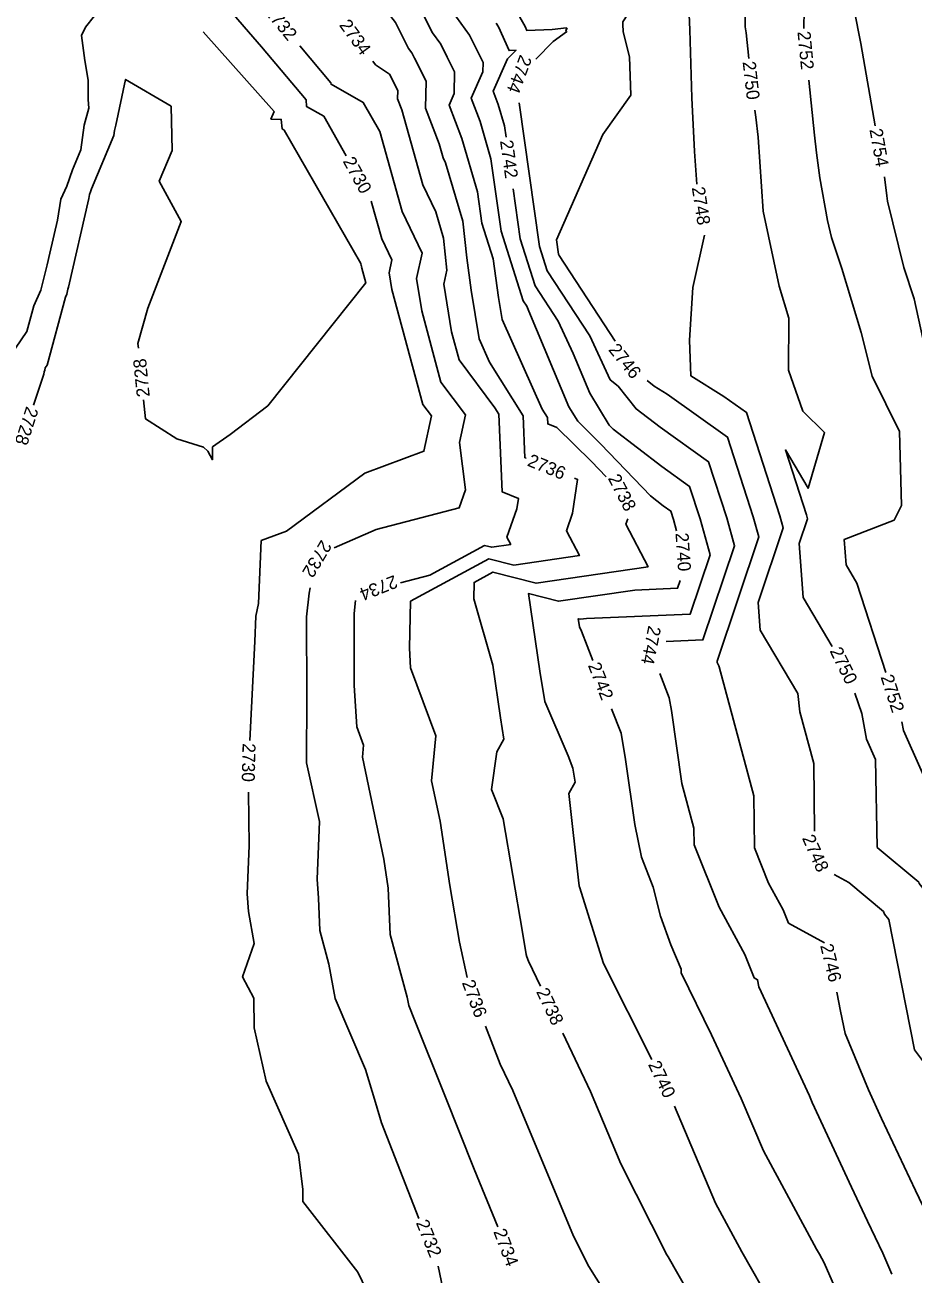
# Model space of a CAD drawing. Extents: x 1326424 to 1329294, y 1001359 to 1003823.
# Drawn here: x 1327989.8 to 1328126.5, y 1002687.1 to 1002879.4 of the extents above; entities that cross this region are included whole.
import ezdxf

# ---------------------------------------------------------------- set-up
doc = ezdxf.new("R2010")
doc.units = 0
doc.layers.add('Prop Rem of Exist Asph Pvmt', color=7, linetype='Continuous')
doc.layers.add('Scratch_Level_3', color=7, linetype='Continuous')

msp = doc.modelspace()

# ---------------------------------------------------------------- linework, layer by layer
at = {"layer": 'Prop Rem of Exist Asph Pvmt'}
for points in [[(1328051.65, 1002889.76), (1328056.26, 1002880.64), (1328058.26, 1002877.87), (1328059.82, 1002874.69), (1328060.32, 1002873.7), (1328060.3, 1002872.23), (1328058.49, 1002868.19), (1328059.86, 1002864.59), (1328061.54, 1002858.85), (1328063.1, 1002847.74), (1328066.52, 1002836.98), (1328067.05, 1002836.17), (1328067.39, 1002835.43), (1328073.55, 1002820.7), (1328074.9, 1002818.48), (1328078.48, 1002814.95), (1328086.09, 1002806.97), (1328088.07, 1002805.44), (1328089.21, 1002804.63), (1328089.64, 1002803.32), (1328090.12, 1002801.59)], [(1328090.67, 1002793.93), (1328090.28, 1002792.77), (1328083.71, 1002792.49), (1328071.92, 1002790.76), (1328067.3, 1002791.95), (1328069.06, 1002779.98), (1328069.81, 1002775.31), (1328073.43, 1002766.96), (1328074.17, 1002765.05), (1328074.53, 1002762.91), (1328073.54, 1002761.16), (1328075.08, 1002747.38), (1328075.1, 1002746.99), (1328075.12, 1002746.92), (1328075.16, 1002746.82), (1328078.89, 1002735.03), (1328086.33, 1002720.24)], [(1328089.78, 1002713.03), (1328096.09, 1002698.14), (1328100.16, 1002690.63), (1328104.83, 1002682.41), (1328112.07, 1002668.46), (1328113.08, 1002666.12), (1328113.65, 1002664.98), (1328121.1, 1002646.94), (1328124.03, 1002640.73), (1328127.87, 1002626.26), (1328128.6, 1002621.38)]]:
    msp.add_lwpolyline(points, dxfattribs=at)
at = {"layer": 'Scratch_Level_3'}
for points in [[(1328085.81, 1002968.7), (1328086.63, 1002966.04), (1328090.35, 1002953.28), (1328091.18, 1002947.31), (1328092.72, 1002942.62), (1328094.13, 1002935.83), (1328095.88, 1002929.47), (1328099.81, 1002908.73), (1328099.75, 1002906.54), (1328099.72, 1002899.04), (1328101.73, 1002895.42), (1328100.93, 1002893.21), (1328102.1, 1002893.19), (1328103.76, 1002892.22), (1328102.34, 1002890.38), (1328100.61, 1002888.24), (1328100.7, 1002879.15), (1328100.82, 1002878.25), (1328101.25, 1002874.29)], [(1328099.88, 1002962.54), (1328098.3, 1002956.73), (1328097.58, 1002953.88), (1328096.58, 1002949.91), (1328095.11, 1002952.77), (1328093.95, 1002955.15), (1328097.18, 1002944.23), (1328098.29, 1002940.01), (1328100.88, 1002931.08), (1328103.34, 1002920.89), (1328106.21, 1002906.84), (1328107.1, 1002905.24), (1328106.44, 1002901.86), (1328106.14, 1002901.14), (1328109.72, 1002898.83), (1328110.63, 1002896.22), (1328111.23, 1002895.33), (1328109.89, 1002890.42), (1328109.34, 1002890.17), (1328109.82, 1002889.18), (1328109.88, 1002887.57), (1328109.7, 1002878.92)], [(1328067.16, 1002959.87), (1328067.39, 1002958.02), (1328073.63, 1002943.56), (1328074.36, 1002941.37), (1328077.21, 1002923.05), (1328078.72, 1002918.69), (1328078.4, 1002909.97), (1328078.39, 1002909.93), (1328077.48, 1002903.22), (1328069.35, 1002892.65), (1328068.98, 1002892.21), (1328068.87, 1002891.89), (1328065.97, 1002880.64), (1328066.81, 1002879.19), (1328067.08, 1002878.59), (1328070.95, 1002878.74), (1328073.19, 1002879.01), (1328073.25, 1002878.89), (1328073.08, 1002878.63), (1328073.18, 1002878.37), (1328071.11, 1002876.89), (1328068.44, 1002874.18)], [(1328083.58, 1002950.21), (1328083.6, 1002950.12), (1328087.44, 1002938.56), (1328087.53, 1002937.99), (1328087.94, 1002936.8), (1328092.09, 1002921.74), (1328093.86, 1002912.39), (1328093.51, 1002900.34), (1328093.5, 1002897.26), (1328094.32, 1002895.78), (1328093.21, 1002892.72), (1328091.7, 1002888.2), (1328091.99, 1002887.57), (1328093.97, 1002887.44), (1328092.27, 1002884.67), (1328091.73, 1002884), (1328091.74, 1002883.05), (1328092.1, 1002880.28), (1328092.12, 1002879.86), (1328092.16, 1002878.68), (1328092.46, 1002868.22), (1328092.87, 1002860), (1328093.21, 1002854.94)], [(1328039.27, 1002859.33), (1328035.79, 1002865.4), (1328033.17, 1002866.88), (1328033.07, 1002867.93), (1328026.24, 1002876.08), (1328020.59, 1002882.62), (1328016.38, 1002886.94), (1328013.75, 1002890.69), (1328009.71, 1002895.02), (1328008.12, 1002896.57), (1328004.64, 1002901.8), (1327996.95, 1002909.58), (1327996.48, 1002909.87), (1327993.92, 1002914.01), (1327990.52, 1002919.55), (1327992, 1002922.95), (1327992.64, 1002931.97), (1327993.9, 1002939.8), (1327994.15, 1002940.85)], [(1328085.17, 1002922.41), (1328087.42, 1002915.9), (1328087.37, 1002914.57), (1328087.34, 1002913.06), (1328086.63, 1002897.49), (1328083.46, 1002886.47), (1328082.73, 1002885.6), (1328082.36, 1002884.53), (1328083.04, 1002884.62), (1328083.86, 1002883.04), (1328083.29, 1002882.15), (1328081.82, 1002879.93), (1328081.84, 1002879.56), (1328081.88, 1002878.4), (1328082.87, 1002874.54), (1328083.08, 1002868.65), (1328078.77, 1002862.61), (1328071.65, 1002846.37), (1328071.95, 1002844.17), (1328072.03, 1002843.95), (1328080.66, 1002830.79)], [(1328029.87, 1002902.46), (1328030.64, 1002901.4), (1328037.21, 1002895.24), (1328038.38, 1002893.35), (1328039.53, 1002892.3), (1328042.38, 1002885.63), (1328046.86, 1002879.81), (1328048.86, 1002875.84), (1328049.36, 1002875.14), (1328049.75, 1002874.35), (1328051.57, 1002870.81), (1328051.49, 1002866.63), (1328053.59, 1002861.15), (1328054.18, 1002859.02), (1328054.56, 1002858.24), (1328057.19, 1002849.24), (1328057.81, 1002843.63), (1328058.51, 1002838.66), (1328059.72, 1002831.16), (1328061.34, 1002827.55), (1328066.5, 1002819.3), (1328066.77, 1002812.84), (1328066.98, 1002812.76)], [(1328041.49, 1002899.21), (1328041.77, 1002899.04), (1328044.25, 1002893.98), (1328045.73, 1002890.53), (1328047.55, 1002888.15), (1328052.56, 1002878.24), (1328053.81, 1002876.51), (1328054.78, 1002874.52), (1328055.94, 1002872.25), (1328055.89, 1002868.89), (1328055.1, 1002867.13), (1328057.06, 1002861.98), (1328059.47, 1002853.75), (1328060.15, 1002848.93), (1328061.89, 1002843.45), (1328062.72, 1002837.52), (1328063.27, 1002834.13), (1328069.45, 1002820.31), (1328070.24, 1002819.05), (1328070.28, 1002818.06), (1328071.7, 1002817.48), (1328077.01, 1002812.25), (1328079.26, 1002809.89)], [(1328116.44, 1002887.03), (1328118.46, 1002876.59), (1328120.71, 1002863.94)], [(1327988.33, 1002829.71), (1327990.12, 1002832.28), (1327991.18, 1002836.21), (1327992.26, 1002838.63), (1327993.23, 1002842.54), (1327993.63, 1002844.31), (1327994.8, 1002849.42), (1327995.32, 1002852.66), (1327996.23, 1002854.66), (1327997.12, 1002857.17), (1327998.4, 1002860.25), (1327998.91, 1002864.01), (1327999.65, 1002866.67), (1327999.55, 1002867.96), (1327999.53, 1002870.97), (1327999.01, 1002873.98), (1327998.5, 1002877.85), (1327999.12, 1002879.09), (1328001.91, 1002882.6)], [(1328008.07, 1002821.77), (1328008.37, 1002818.81), (1328013.17, 1002815.77), (1328017.27, 1002814.49), (1328017.96, 1002813.88), (1328018.7, 1002812.55), (1328018.67, 1002814.5), (1328021.42, 1002816.41), (1328027.17, 1002820.81), (1328042.26, 1002839.78), (1328041.66, 1002842.02), (1328041.63, 1002842.14), (1328041.66, 1002842.25), (1328041.58, 1002842.41), (1328041.49, 1002842.73), (1328029.72, 1002863.28), (1328029.41, 1002863.45), (1328029.27, 1002864.91), (1328027.68, 1002864.97), (1328028.15, 1002866.13), (1328017.23, 1002878.4)], [(1328062.33, 1002879.75), (1328062.68, 1002879.14), (1328064.34, 1002875.51), (1328065.41, 1002875.55), (1328064.11, 1002874.23), (1328061.88, 1002869.25), (1328062.66, 1002867.21), (1328063.62, 1002863.94), (1328063.86, 1002862.16)], [(1328032.11, 1002876.26), (1328036.91, 1002870.54), (1328036.94, 1002870.32), (1328041.87, 1002867.53), (1328044.42, 1002863.07), (1328047.88, 1002850.72), (1328050.94, 1002844.34), (1328050.08, 1002840.43), (1328050.88, 1002835.48), (1328053.85, 1002824.48), (1328057.62, 1002819.43), (1328056.71, 1002815.19), (1328057.62, 1002807.89), (1328056.65, 1002805.14), (1328043.86, 1002801.78), (1328037.38, 1002798.97)], [(1328043.34, 1002873.89), (1328043.77, 1002873.3), (1328045.9, 1002871.88), (1328047.19, 1002869.36), (1328047.16, 1002868.07), (1328047.81, 1002866.39), (1328051.03, 1002854.87), (1328053.05, 1002850.67), (1328054.23, 1002846.64), (1328054.77, 1002841.72), (1328054.3, 1002839.57), (1328055.49, 1002832.22), (1328056.65, 1002827.9), (1328062.15, 1002820.52), (1328062.76, 1002819.55), (1328063.25, 1002807.62), (1328065.78, 1002806.59), (1328065.54, 1002804.97), (1328064.01, 1002800.62), (1328064.59, 1002799.5), (1328061.66, 1002799.07), (1328060.53, 1002799.36), (1328052.12, 1002794.78), (1328047.6, 1002793.6)], [(1327991.14, 1002820.94), (1327992.73, 1002825.7), (1327992.77, 1002826.06), (1327992.85, 1002826.35), (1327992.94, 1002826.69), (1327993.2, 1002827.07), (1327996.03, 1002837.54), (1327996.24, 1002838.01), (1327996.43, 1002838.78), (1327996.5, 1002839.12), (1327999.62, 1002852.74), (1327999.72, 1002853.37), (1327999.9, 1002853.76), (1328000.07, 1002854.25), (1328003.48, 1002862.46), (1328003.58, 1002863.19), (1328003.81, 1002864.03), (1328005.3, 1002871.06), (1328012.29, 1002866.95), (1328012.46, 1002860.15), (1328010.49, 1002855.42), (1328013.86, 1002849.19), (1328008.7, 1002835.86), (1328007.19, 1002830.45), (1328007.26, 1002829.72)], [(1328110.47, 1002870.96), (1328111.35, 1002862.51), (1328111.68, 1002859.77), (1328112.17, 1002855.94), (1328113.35, 1002849.37), (1328113.99, 1002846.76), (1328115.54, 1002841.97), (1328118.52, 1002832.11), (1328120.24, 1002825.39), (1328124.43, 1002816.88), (1328124.73, 1002805.52), (1328123.6, 1002803.24), (1328115.93, 1002800.27), (1328116.2, 1002796.36), (1328117.88, 1002793.54), (1328122.32, 1002779.81)], [(1328065.91, 1002867.46), (1328069, 1002845.36), (1328070.19, 1002841.63), (1328076.77, 1002831.59), (1328079.88, 1002824.85), (1328081.15, 1002823.86), (1328083.89, 1002820.37), (1328087.59, 1002817.53), (1328095.04, 1002812.22), (1328097.83, 1002803.62), (1328099.04, 1002799.29), (1328094.16, 1002784.81), (1328088.5, 1002784.58)], [(1328102.16, 1002866.35), (1328102.3, 1002865.25), (1328102.69, 1002862.16), (1328103.46, 1002850.81), (1328105.9, 1002839.27), (1328107.41, 1002834.34), (1328107.34, 1002826.35), (1328109.56, 1002819.99), (1328112.9, 1002816.72), (1328110.35, 1002808.15), (1328106.88, 1002814.05), (1328110.12, 1002804.07), (1328110.29, 1002803.46), (1328109.01, 1002799.65), (1328109.58, 1002791.34), (1328114.08, 1002783.78)], [(1328122.12, 1002856.07), (1328122.47, 1002853.15), (1328122.61, 1002852.34), (1328125.1, 1002842.15), (1328126.67, 1002837.3), (1328128, 1002831.19), (1328135, 1002818.38), (1328135.31, 1002816.57), (1328139.53, 1002800.99), (1328140.12, 1002796.22), (1328139.36, 1002794.3), (1328140.28, 1002771.27), (1328140.3, 1002769.86), (1328140.99, 1002768.46), (1328141.39, 1002767.82), (1328143.6, 1002759.94)], [(1328064.97, 1002854.24), (1328066.05, 1002846.55), (1328068.35, 1002839.3), (1328071.91, 1002833.88), (1328074.2, 1002828.91), (1328076.78, 1002822.77), (1328079.75, 1002817.85), (1328079.94, 1002817.66), (1328080.35, 1002817.23), (1328087.83, 1002811.49), (1328092.13, 1002808.43), (1328093.73, 1002803.47), (1328095.29, 1002797.9), (1328092.22, 1002788.79), (1328076.24, 1002788.12), (1328075.34, 1002787.99), (1328074.99, 1002788.08), (1328075.12, 1002787.16), (1328075.18, 1002786.8), (1328075.46, 1002786.17), (1328077.22, 1002781.66)], [(1328024.43, 1002769.35), (1328025.21, 1002784.58), (1328025.35, 1002788.47), (1328025.75, 1002790.4), (1328026.18, 1002800.09), (1328030.05, 1002801.56), (1328042.11, 1002810.49), (1328051.22, 1002813.84), (1328052.38, 1002819.28), (1328051.05, 1002821.06), (1328046.27, 1002838.75), (1328045.86, 1002841.29), (1328046.3, 1002843.29), (1328044.73, 1002846.56), (1328043.12, 1002852.33)], [(1328094.44, 1002847.11), (1328092.6, 1002839.03), (1328092.13, 1002830.95), (1328092.32, 1002825.44), (1328097.39, 1002822.29), (1328100.87, 1002819.81), (1328106.02, 1002803.92), (1328106.54, 1002802.07), (1328102.67, 1002790.59), (1328102.97, 1002786.33), (1328108.76, 1002776.58), (1328109.1, 1002773.76), (1328111.26, 1002765.77), (1328111.37, 1002755.37)], [(1328085.59, 1002824.72), (1328086.69, 1002823.86), (1328088.66, 1002822.64), (1328097.96, 1002816.02), (1328101.93, 1002803.77), (1328102.79, 1002800.68), (1328096.34, 1002781.52), (1328096.35, 1002781.31), (1328096.64, 1002780.82), (1328096.66, 1002780.68), (1328102.02, 1002760.81), (1328102.11, 1002752.82), (1328104.28, 1002747.37), (1328106.53, 1002743.27), (1328107.34, 1002741.22), (1328112.9, 1002738.19)], [(1328074.38, 1002809.72), (1328074.87, 1002809.52), (1328074.11, 1002804.32), (1328073.16, 1002801.62), (1328075.16, 1002797.78), (1328065.08, 1002796.3), (1328061.19, 1002797.3), (1328049.18, 1002790.76), (1328048.99, 1002783.55), (1328049.18, 1002780.52), (1328053.04, 1002770.06), (1328052.4, 1002763.14), (1328053.72, 1002756.89), (1328055.19, 1002747), (1328056.68, 1002738.31), (1328057.87, 1002732.85)], [(1328082.6, 1002803.43), (1328082.31, 1002802.62), (1328085.73, 1002796.06), (1328068.5, 1002793.53), (1328061.85, 1002795.24), (1328058.95, 1002793.66), (1328058.89, 1002791.12), (1328061.81, 1002780.92), (1328063, 1002772.8), (1328063.53, 1002769.53), (1328062.44, 1002767.56), (1328061.61, 1002761.81), (1328063.41, 1002757.26), (1328066.4, 1002739.81), (1328066.98, 1002736.38), (1328067.06, 1002736.05), (1328067.32, 1002735.36), (1328069.17, 1002731.5)], [(1328033.73, 1002792.83), (1328033.58, 1002792.03), (1328033.17, 1002788.38), (1328033.2, 1002776.23), (1328033.13, 1002765.87), (1328035.13, 1002756.86), (1328034.8, 1002747.98), (1328034.98, 1002745.05), (1328035.21, 1002740.1), (1328036.6, 1002734.92), (1328037.57, 1002729.62), (1328042.21, 1002718.69), (1328043.76, 1002713.61), (1328044.71, 1002710.48), (1328050.45, 1002695.78)], [(1328040.69, 1002790.87), (1328040.47, 1002788.89), (1328040.49, 1002777.81), (1328040.88, 1002771.44), (1328041.93, 1002768.61), (1328041.76, 1002766.74), (1328045.05, 1002751.09), (1328045.72, 1002746.61), (1328046.04, 1002739.45), (1328048.63, 1002729.85), (1328048.92, 1002728.53), (1328049.77, 1002726.36), (1328054.45, 1002714.71), (1328058.98, 1002703.38), (1328062.58, 1002694.5)], [(1328087.52, 1002779.66), (1328088.99, 1002775.9), (1328089.32, 1002773.93), (1328090.93, 1002762.71), (1328092.78, 1002755.86), (1328092.81, 1002753.28), (1328096.65, 1002743.67), (1328100.63, 1002736.41), (1328102.06, 1002732.79), (1328102.58, 1002732.51), (1328102.58, 1002732.48), (1328102.79, 1002731.4), (1328110.58, 1002714.65), (1328111.01, 1002713.6), (1328117.05, 1002700.58), (1328119.52, 1002695.34), (1328121.85, 1002690.44), (1328123.26, 1002687.2)], [(1328117.58, 1002776.64), (1328118.61, 1002773.48), (1328119.34, 1002769.54), (1328120.73, 1002766.41), (1328121.01, 1002752.87), (1328127.4, 1002747.54), (1328127.47, 1002747.31), (1328129.81, 1002744.37), (1328132.2, 1002732.26), (1328136.45, 1002726.71), (1328140.9, 1002715.49), (1328143.38, 1002707.66), (1328146.22, 1002703.17), (1328150.33, 1002698.94), (1328150.72, 1002698.32), (1328154.55, 1002688.03), (1328154.83, 1002687.24)], [(1328080.12, 1002774.2), (1328081.58, 1002770.48), (1328082.26, 1002766.42), (1328083.71, 1002756.38), (1328084.7, 1002751.39), (1328086.49, 1002746.78), (1328087.65, 1002742.3), (1328089.21, 1002737.87), (1328090.81, 1002734.15), (1328090.83, 1002733.58), (1328095.51, 1002724.04), (1328100.07, 1002714.25), (1328103.48, 1002706.18), (1328111.68, 1002691.07), (1328112.13, 1002690.28), (1328112.83, 1002688.92), (1328116.01, 1002681.64)], [(1328124.78, 1002772.2), (1328125.03, 1002770.89), (1328130.67, 1002758.18), (1328130.76, 1002753.81), (1328132.82, 1002752.09), (1328132.85, 1002752.01), (1328136.84, 1002746.97), (1328137.67, 1002742.78), (1328144.77, 1002733.53), (1328147.36, 1002726.98), (1328152.65, 1002710.29), (1328154.21, 1002707.82), (1328156.81, 1002705.15), (1328158.89, 1002699.89), (1328163.51, 1002687.69), (1328163.57, 1002687.52), (1328163.67, 1002687.34), (1328165.77, 1002682.84)], [(1328045.44, 1002667.62), (1328046.41, 1002668.51), (1328044.57, 1002676.62), (1328044.43, 1002677.26), (1328043.06, 1002683.36), (1328041.03, 1002687.49), (1328032.58, 1002698.39), (1328032.6, 1002700.23), (1328031.92, 1002705.65), (1328026.93, 1002716.92), (1328025.07, 1002725.12), (1328025.02, 1002729.67), (1328023.32, 1002732.98), (1328025.08, 1002738.08), (1328024.2, 1002743.03), (1328024.03, 1002745.75), (1328024.3, 1002753.16), (1328024.24, 1002761.36)], [(1328114.39, 1002748.69), (1328116.61, 1002747.47), (1328121.98, 1002743), (1328122.1, 1002742.6), (1328122.77, 1002741.76), (1328126.72, 1002721.73), (1328128.13, 1002719.9), (1328133.06, 1002707.47), (1328134.32, 1002704.79), (1328135.78, 1002701.73), (1328139.57, 1002694.98), (1328141.54, 1002691.83), (1328142.93, 1002688.09), (1328149.25, 1002676.29), (1328155.73, 1002664.7), (1328157.75, 1002660.76)], [(1328114.77, 1002730.6), (1328115.33, 1002727.66), (1328116.07, 1002724.26), (1328119.65, 1002715.55), (1328121.67, 1002711.17), (1328126.92, 1002700.06), (1328131.86, 1002689.67), (1328133.73, 1002685.39), (1328139.78, 1002673.17), (1328143.05, 1002667.06), (1328144.71, 1002664.09), (1328151.02, 1002651.78), (1328155.06, 1002639.4)], [(1328060.69, 1002725.37), (1328062.98, 1002719.5), (1328064.91, 1002715.46), (1328074.27, 1002693.07), (1328076.63, 1002688.39), (1328089.92, 1002667.23), (1328090.23, 1002666.69), (1328090.39, 1002666.38), (1328100.14, 1002647.09), (1328103.02, 1002640.4), (1328104.42, 1002635.75)], [(1328072.62, 1002724.29), (1328076.89, 1002715.33), (1328081.55, 1002704.17), (1328088.63, 1002690.17), (1328088.8, 1002689.89), (1328097.53, 1002674.55), (1328102.14, 1002665.66), (1328106.57, 1002656.89), (1328113.54, 1002640.74), (1328113.63, 1002640.46), (1328114.07, 1002638.78), (1328115.31, 1002634.09)], [(1328053.43, 1002688.42), (1328056.34, 1002674.45), (1328059.11, 1002666.27), (1328059.13, 1002666.21), (1328060.57, 1002660.94), (1328063.55, 1002652.83), (1328064.09, 1002648.12), (1328066.57, 1002638.55), (1328069.84, 1002630), (1328072.02, 1002618.69), (1328072.32, 1002615.04), (1328072.67, 1002603.2), (1328073.66, 1002598.77), (1328074.68, 1002591.26)]]:
    msp.add_lwpolyline(points, dxfattribs=at)

# ---------------------------------------------------------------- texts
at = {"layer": 'Prop Rem of Exist Asph Pvmt'}
for rotation, p in [(274.0953, (1328089.94, 1002801.24)), (295.5811, (1328085.68, 1002719.47))]:
    msp.add_text('2740', height=2, rotation=rotation, dxfattribs=at).set_placement(p)
at = {"layer": 'Scratch_Level_3'}
for s, rotation, p in [('2732', 309.4317, (1328026.54, 1002881.46)), ('2734', 305.9754, (1328038.1, 1002879.42)), ('2752', 275.5328, (1328108.72, 1002878.41)), ('2744', 249.3315, (1328066.04, 1002874.99)), ('2750', 276.5392, (1328100.28, 1002873.76)), ('2754', 280.1131, (1328119.8, 1002863.35)), ('2742', 277.9734, (1328062.93, 1002861.61)), ('2730', 298.7655, (1328038.68, 1002858.49)), ('2748', 278.925, (1328092.45, 1002854.41)), ('2746', 309.122, (1328079.53, 1002829.43)), ('2728', 95.8151, (1328009.03, 1002822.28)), ('2728', 252.1608, (1327990.03, 1002820.86)), ('2736', 337.7195, (1328067.01, 1002811.66)), ('2738', 297.3457, (1328079.5, 1002809.69)), ('2732', 239.2379, (1328035.44, 1002800.33)), ('2734', 201.6126, (1328046.66, 1002794.83)), ('2744', 258.7025, (1328085.79, 1002787.1)), ('2750', 296.17, (1328113.64, 1002783.12)), ('2742', 291.3112, (1328076.44, 1002780.9)), ('2752', 287.9177, (1328121.5, 1002779.11)), ('2730', 268.6296, (1328023.31, 1002768.93)), ('2748', 294.2441, (1328109.39, 1002754.3)), ('2746', 283.8454, (1328112.2, 1002737.77)), ('2736', 290.697, (1328057.04, 1002732.06)), ('2738', 295.5324, (1328068.46, 1002730.67)), ('2732', 292.047, (1328049.96, 1002695.11)), ('2734', 290.7584, (1328061.88, 1002693.76))]:
    msp.add_text(s, height=2, rotation=rotation, dxfattribs=at).set_placement(p)

doc.saveas('drawing.dxf')
